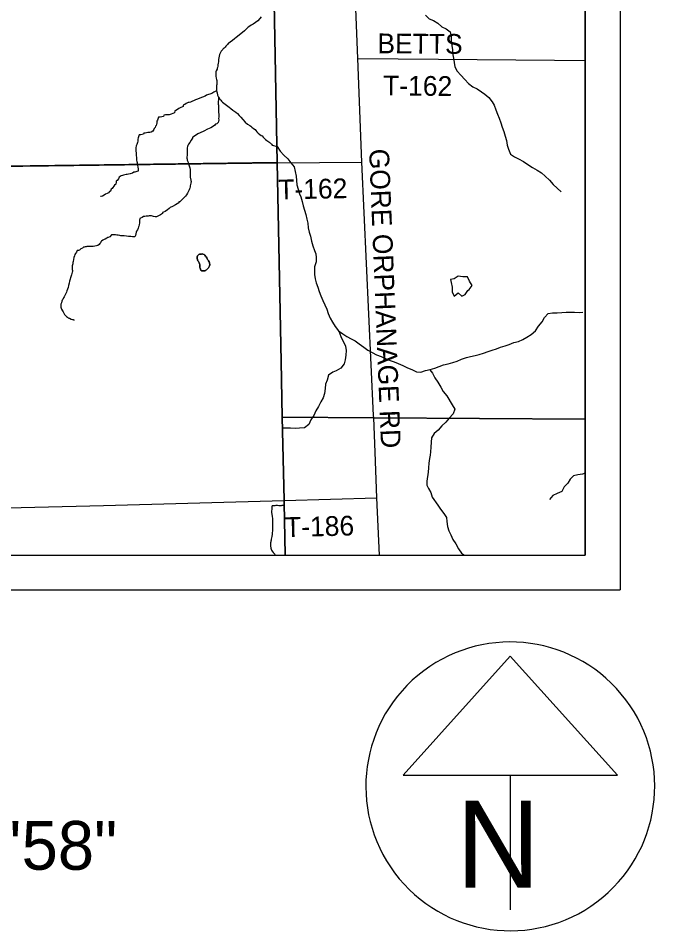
# Model space of a CAD drawing. Extents: x 0 to 34, y 0 to 22.
# Drawn here: x 7.272 to 9.099, y 13.02 to 15.642 of the extents above; entities that cross this region are included whole.
import ezdxf

# ---------------------------------------------------------------- set-up
doc = ezdxf.new("R2010")
doc.units = 0
for name, color, linetype in [('GM_X_Corporation', 7, 'Continuous'), ('GM_X_County_Road', 7, 'Continuous'), ('GM_X_County_Road_Text', 7, 'Continuous'), ('GM_X_Minor_Lake', 7, 'Continuous'), ('GM_X_Minor_River', 7, 'Continuous'), ('GM_X_Township_Road', 7, 'Continuous'), ('GM_X_Township_Road_Text', 7, 'Continuous'), ('SH_Data', 7, 'Continuous'), ('SH_Text', 7, 'Continuous')]:
    doc.layers.add(name, color=color, linetype=linetype)

msp = doc.modelspace()

# ---------------------------------------------------------------- linework, layer by layer
at = {"layer": 'GM_X_Corporation'}
for points in [[(7.992, 16.4534), (8.0153, 15.2273), (8.0262, 14.6555), (8.0297, 14.4963), (8.0349, 14.2572), (8.035, 14.2498), (8.0383, 14.1), (8.9, 14.1), (8.9, 20.9)], [(2.1, 20.2456), (2.1, 14.1), (8.0383, 14.1), (8.035, 14.2498), (8.0349, 14.2572), (8.0297, 14.4963), (8.0262, 14.6555), (8.0153, 15.2273), (7.992, 16.4534)], [(5.9099, 15.7256), (5.9099, 15.2138), (6.1026, 15.2145), (6.7394, 15.212), (6.9496, 15.2134), (8.0153, 15.2273), (7.992, 16.4534)]]:
    msp.add_lwpolyline(points, dxfattribs=at)
for points in [[(7.9196, 19.2769), (7.9387, 18.4008), (7.951, 17.9078), (7.9575, 17.6697), (7.9659, 17.2939), (7.973, 17.0583), (7.9733, 17.0489), (7.9799, 16.8298), (7.992, 16.4534), (8.0153, 15.2273), (8.0262, 14.6555), (8.0297, 14.4963), (8.2922, 14.4944), (8.9, 14.4898), (8.9, 19.6997), (8.7801, 19.7002), (8.7801, 19.2769)], [(3.6901, 15.2048), (3.5209, 15.2041), (2.7366, 15.2014), (2.7422, 14.8151), (2.7753, 14.1537), (2.7761, 14.1), (8.0383, 14.1), (8.035, 14.2498), (8.0349, 14.2572), (8.0297, 14.4963), (8.0262, 14.6555), (8.0153, 15.2273), (6.9496, 15.2134), (6.7394, 15.212), (6.1026, 15.2145), (5.9099, 15.2138), (5.9099, 15.0085), (3.6901, 15.0085)], [(8.0383, 14.1), (8.9, 14.1), (8.9, 14.4898), (8.2922, 14.4944), (8.0297, 14.4963), (8.0349, 14.2572), (8.035, 14.2498)]]:
    msp.add_lwpolyline(points, close=True, dxfattribs=at)
at = {"layer": 'GM_X_County_Road'}
for p, q in [((8.2583, 15.2291), (8.2463, 15.5263)), ((8.2921, 14.5007), (8.2583, 15.2291))]:
    msp.add_line(p, q, dxfattribs=at)
for points in [[(8.2463, 15.5263), (8.2291, 15.9577), (8.215, 16.333), (8.206, 16.5759), (8.1937, 16.9162), (8.1904, 17.0478)], [(8.3094, 14.1), (8.3012, 14.2639), (8.2967, 14.3954), (8.2924, 14.4938), (8.2921, 14.5007)], [(6.9836, 14.2295), (7.1599, 14.2339), (7.5161, 14.2424), (8.0351, 14.2567)]]:
    msp.add_lwpolyline(points, dxfattribs=at)
at = {"layer": 'GM_X_Minor_Lake'}
for points in [[(7.7888, 14.9624), (7.788, 14.9615), (7.7861, 14.9592), (7.7853, 14.9569), (7.7853, 14.9546), (7.7853, 14.9527), (7.7854, 14.952)], [(7.7854, 14.952), (7.7853, 14.9527), (7.7853, 14.9546), (7.7853, 14.9569), (7.7861, 14.9592), (7.788, 14.9615), (7.7888, 14.9624)], [(7.7854, 14.952), (7.7876, 14.9455), (7.7887, 14.9436), (7.7898, 14.9417), (7.791, 14.939), (7.7925, 14.9363), (7.7928, 14.9344), (7.7928, 14.9321), (7.7928, 14.9287), (7.7932, 14.9264), (7.7939, 14.9238), (7.7947, 14.9211), (7.7962, 14.9184), (7.7988, 14.9169), (7.8019, 14.9161), (7.8038, 14.9161), (7.8057, 14.9161), (7.808, 14.9165), (7.8107, 14.918), (7.8126, 14.9191), (7.816, 14.9229), (7.8179, 14.9251), (7.8187, 14.927), (7.8202, 14.9289), (7.8206, 14.9312), (7.8214, 14.9335), (7.8214, 14.9354), (7.821, 14.9373), (7.8207, 14.9392), (7.8196, 14.9422), (7.818, 14.9449), (7.8169, 14.9468), (7.8154, 14.9491), (7.8143, 14.951), (7.8128, 14.9541), (7.8109, 14.9564), (7.8093, 14.9583), (7.8075, 14.961), (7.8052, 14.9629), (7.8018, 14.9644), (7.7995, 14.9648), (7.798, 14.9645)], [(7.798, 14.9645), (7.7995, 14.9648), (7.8018, 14.9644), (7.8052, 14.9629), (7.8075, 14.961), (7.8093, 14.9583), (7.8109, 14.9564), (7.8128, 14.9541), (7.8143, 14.951), (7.8154, 14.9491), (7.8169, 14.9468), (7.818, 14.9449), (7.8196, 14.9422), (7.8207, 14.9392), (7.821, 14.9373), (7.8214, 14.9354), (7.8214, 14.9335), (7.8206, 14.9312), (7.8202, 14.9289), (7.8187, 14.927), (7.8179, 14.9251), (7.816, 14.9229), (7.8126, 14.9191), (7.8107, 14.918), (7.808, 14.9165), (7.8057, 14.9161), (7.8038, 14.9161), (7.8019, 14.9161), (7.7988, 14.9169), (7.7962, 14.9184), (7.7947, 14.9211), (7.7939, 14.9238), (7.7932, 14.9264), (7.7928, 14.9287), (7.7928, 14.9321), (7.7928, 14.9344), (7.7925, 14.9363), (7.791, 14.939), (7.7898, 14.9417), (7.7887, 14.9436), (7.7876, 14.9455), (7.7854, 14.952)], [(7.798, 14.9645), (7.7922, 14.9645), (7.7899, 14.9637), (7.7888, 14.9624)], [(7.7888, 14.9624), (7.7899, 14.9637), (7.7922, 14.9645), (7.798, 14.9645)], [(8.5627, 14.8597), (8.5665, 14.8627), (8.5747, 14.874), (8.5672, 14.887), (8.5617, 14.8993), (8.548, 14.8991), (8.5351, 14.9012), (8.5235, 14.893), (8.5124, 14.892)], [(8.5124, 14.892), (8.515, 14.8832), (8.5175, 14.8695), (8.5177, 14.8558), (8.5232, 14.8432), (8.5348, 14.8529), (8.5453, 14.844), (8.5553, 14.8484), (8.5627, 14.8597)], [(8.5124, 14.892), (8.515, 14.8832), (8.5175, 14.8695), (8.5177, 14.8558), (8.5232, 14.8432), (8.5348, 14.8529), (8.5453, 14.844), (8.5553, 14.8484), (8.5627, 14.8597)], [(8.5627, 14.8597), (8.5665, 14.8627), (8.5747, 14.874), (8.5672, 14.887), (8.5617, 14.8993), (8.548, 14.8991), (8.5351, 14.9012), (8.5235, 14.893), (8.5125, 14.892)]]:
    msp.add_lwpolyline(points, dxfattribs=at)
at = {"layer": 'GM_X_Minor_River'}
for points in [[(7.9695, 15.646), (7.9653, 15.6418), (7.9596, 15.635), (7.9531, 15.6297), (7.9466, 15.6252), (7.9405, 15.6222), (7.9362, 15.6196), (7.932, 15.6162), (7.9267, 15.6113), (7.9209, 15.606), (7.9152, 15.6015), (7.8976, 15.5871), (7.8922, 15.5834), (7.8865, 15.5781), (7.8804, 15.5735), (7.8758, 15.5709), (7.8739, 15.5694), (7.872, 15.5671), (7.8701, 15.5649), (7.8681, 15.5622), (7.8658, 15.5592), (7.8628, 15.5562), (7.8601, 15.5543), (7.8586, 15.5524), (7.857, 15.5505), (7.8543, 15.5475), (7.8532, 15.5456), (7.8513, 15.5422), (7.8509, 15.5403), (7.8497, 15.5376), (7.8489, 15.5334), (7.8478, 15.5285), (7.847, 15.5236), (7.847, 15.519), (7.8462, 15.5171), (7.8454, 15.5129), (7.845, 15.5087), (7.8446, 15.5042), (7.8438, 15.5008), (7.843, 15.4989), (7.8423, 15.4962), (7.84, 15.4913), (7.8392, 15.4886), (7.8388, 15.4852), (7.8388, 15.4803), (7.8391, 15.4753), (7.8398, 15.4696), (7.8413, 15.4658), (7.8417, 15.4631), (7.8421, 15.4601), (7.8421, 15.4555), (7.8417, 15.4517), (7.8413, 15.4487), (7.8412, 15.4453), (7.8408, 15.4422), (7.8408, 15.4361), (7.8412, 15.4331), (7.8423, 15.4281), (7.8438, 15.4213), (7.8468, 15.4152), (7.8498, 15.4106), (7.8513, 15.4087), (7.8532, 15.4064), (7.8555, 15.4037), (7.8585, 15.401), (7.8619, 15.398), (7.8654, 15.3957), (7.8692, 15.3922), (7.8733, 15.3895), (7.8771, 15.3864), (7.8817, 15.383), (7.8874, 15.3776), (7.8961, 15.3726), (7.9014, 15.3684), (7.9059, 15.3631), (7.9109, 15.3577), (7.9166, 15.3512), (7.923, 15.3439), (7.9298, 15.3382), (7.9363, 15.3343), (7.9397, 15.3324), (7.9427, 15.3293), (7.9473, 15.3255), (7.9518, 15.3224), (7.9541, 15.3194), (7.9567, 15.3155), (7.9609, 15.3117), (7.9655, 15.3083), (7.9696, 15.3056), (7.9719, 15.304), (7.9749, 15.3002), (7.9776, 15.2975), (7.9795, 15.296)], [(8.4412, 15.6509), (8.4517, 15.6409), (8.4642, 15.6361), (8.4766, 15.6276), (8.4875, 15.6171), (8.5, 15.6116), (8.5121, 15.6031), (8.5149, 15.5901), (8.5148, 15.5764), (8.5169, 15.5635), (8.519, 15.5513), (8.5192, 15.5372), (8.5213, 15.5277), (8.523, 15.5147), (8.5255, 15.5021), (8.5315, 15.4902), (8.5423, 15.4787), (8.5536, 15.4659), (8.5641, 15.4551), (8.5769, 15.4451), (8.589, 15.4392), (8.6014, 15.431), (8.6113, 15.4244), (8.6233, 15.4147), (8.6326, 15.4024), (8.6378, 15.3928), (8.643, 15.379), (8.6478, 15.3668), (8.6522, 15.3549), (8.6569, 15.3419), (8.6609, 15.3293), (8.6661, 15.3163), (8.6697, 15.303), (8.6734, 15.2907), (8.6758, 15.2778), (8.6791, 15.2656), (8.6854, 15.2518), (8.6963, 15.2444), (8.708, 15.2385), (8.722, 15.2307), (8.7348, 15.2217), (8.748, 15.2132), (8.762, 15.2054), (8.7741, 15.1983), (8.785, 15.1887), (8.7967, 15.1767), (8.8079, 15.1647), (8.8192, 15.1535), (8.8308, 15.1431)], [(7.8412, 15.4331), (7.8366, 15.4316), (7.8332, 15.4293), (7.8278, 15.4263), (7.8118, 15.4211), (7.808, 15.4181), (7.8007, 15.4155), (7.7927, 15.4125), (7.7866, 15.4095), (7.7809, 15.4073), (7.777, 15.4058), (7.7747, 15.405), (7.7717, 15.4035), (7.766, 15.4013), (7.7622, 15.4005), (7.7591, 15.4002), (7.7534, 15.3968), (7.7503, 15.3945), (7.7469, 15.393), (7.745, 15.3927), (7.7449, 15.3881), (7.7362, 15.3851), (7.7323, 15.3832), (7.7289, 15.3798), (7.7243, 15.3772), (7.7213, 15.3761), (7.7205, 15.3708), (7.7109, 15.3666), (7.7048, 15.3648), (7.7014, 15.3648), (7.6945, 15.3645), (7.6896, 15.3637), (7.6888, 15.3603), (7.6793, 15.3581), (7.6747, 15.3578), (7.6716, 15.3494), (7.6697, 15.346), (7.6693, 15.3418), (7.6693, 15.3399), (7.6689, 15.3376), (7.6677, 15.3342), (7.6658, 15.3316), (7.6643, 15.3285), (7.6623, 15.3251), (7.6608, 15.3225), (7.6581, 15.3179), (7.6535, 15.3149), (7.6493, 15.3134), (7.647, 15.3138), (7.6436, 15.3135), (7.6402, 15.3131), (7.6356, 15.3124), (7.6326, 15.3124), (7.6314, 15.309), (7.6238, 15.3071), (7.6188, 15.3068), (7.6157, 15.2981), (7.6153, 15.295), (7.6149, 15.2931), (7.6145, 15.2889), (7.6137, 15.2848), (7.6122, 15.2798), (7.6106, 15.2753), (7.6095, 15.27), (7.6094, 15.2627), (7.6101, 15.2521), (7.6105, 15.2498), (7.6105, 15.2464), (7.6109, 15.2426), (7.6112, 15.2384), (7.6116, 15.2346), (7.6123, 15.2308), (7.6127, 15.2277), (7.613, 15.2228), (7.6142, 15.219), (7.6145, 15.2152), (7.6153, 15.2129), (7.6156, 15.211), (7.6156, 15.2087), (7.6156, 15.2064), (7.6156, 15.203), (7.6125, 15.2019), (7.6095, 15.2011), (7.6064, 15.2), (7.6038, 15.1996), (7.5999, 15.1966), (7.5931, 15.1952), (7.5881, 15.194), (7.5839, 15.1933), (7.5816, 15.1929), (7.5778, 15.1922), (7.574, 15.1911), (7.571, 15.1904), (7.5675, 15.1892), (7.5641, 15.187), (7.561, 15.1859), (7.5599, 15.1809), (7.5553, 15.176), (7.553, 15.1737), (7.5526, 15.1715), (7.5518, 15.1658)], [(7.8468, 15.4152), (7.8459, 15.3954), (7.8463, 15.3924), (7.8463, 15.3897), (7.8463, 15.3851), (7.8462, 15.3802), (7.8462, 15.3771), (7.8466, 15.3733), (7.8469, 15.3703), (7.8473, 15.368), (7.8473, 15.3661), (7.8477, 15.3634), (7.8473, 15.3608), (7.8473, 15.3577), (7.8469, 15.3539), (7.8472, 15.3501), (7.8472, 15.3482), (7.8468, 15.346), (7.8453, 15.3422), (7.8414, 15.3388), (7.8384, 15.338), (7.8361, 15.3354), (7.8319, 15.3316), (7.825, 15.3275), (7.8151, 15.323), (7.8048, 15.3173), (7.7941, 15.3128), (7.7872, 15.3098), (7.7746, 15.3016), (7.7723, 15.3008), (7.7723, 15.2978), (7.7681, 15.2921), (7.7642, 15.2853), (7.7604, 15.28), (7.7585, 15.2766), (7.7573, 15.2732), (7.7565, 15.2697), (7.7565, 15.2644), (7.7568, 15.2606), (7.7568, 15.2572), (7.7568, 15.2526), (7.7564, 15.2477), (7.7556, 15.2439), (7.756, 15.2401), (7.7567, 15.2374), (7.7571, 15.2344), (7.7582, 15.2306), (7.7597, 15.2264), (7.7612, 15.221), (7.7642, 15.2123), (7.7649, 15.2073), (7.7653, 15.2027), (7.7653, 15.1986), (7.7652, 15.1925), (7.7652, 15.186), (7.7663, 15.1811), (7.7671, 15.1788), (7.7674, 15.1757), (7.7678, 15.1731), (7.7674, 15.1685), (7.7662, 15.1643), (7.7655, 15.1609), (7.7651, 15.1582), (7.7643, 15.1544), (7.7631, 15.1522), (7.7624, 15.1495), (7.7604, 15.145), (7.7577, 15.1397), (7.7547, 15.1344), (7.752, 15.1309), (7.7351, 15.1147), (7.7325, 15.1143), (7.7324, 15.1121), (7.7229, 15.106), (7.7145, 15.1012), (7.708, 15.0982), (7.7049, 15.0955), (7.7, 15.0914), (7.6938, 15.0865), (7.6885, 15.0846), (7.6862, 15.0842), (7.6858, 15.0812), (7.6801, 15.0774), (7.6763, 15.0755), (7.6743, 15.0744), (7.6709, 15.0725), (7.6682, 15.0714), (7.6644, 15.0714), (7.6595, 15.0726), (7.6542, 15.0742), (7.65, 15.0746), (7.6477, 15.0746), (7.6442, 15.0739), (7.6393, 15.0731), (7.6347, 15.0724), (7.6309, 15.0721), (7.6275, 15.0698), (7.6225, 15.0679)], [(7.9795, 15.296), (7.9814, 15.2933), (7.9852, 15.2906), (7.9886, 15.2887), (7.9909, 15.2872), (7.9932, 15.2853), (7.9954, 15.2841), (7.9988, 15.2803), (8.0011, 15.2776), (8.0154, 15.2738)], [(8.0154, 15.2738), (8.0238, 15.2599), (8.0343, 15.2487), (8.0456, 15.2383), (8.0546, 15.2264), (8.0635, 15.2148), (8.0672, 15.2014), (8.0696, 15.1885), (8.071, 15.1759), (8.072, 15.1633), (8.0756, 15.1507), (8.0796, 15.1381), (8.0829, 15.1286), (8.0865, 15.116), (8.0894, 15.103), (8.0934, 15.0904), (8.0974, 15.0782), (8.1007, 15.0652), (8.1028, 15.053), (8.1045, 15.0397), (8.1074, 15.0274), (8.111, 15.0156), (8.1139, 15.0019), (8.1179, 14.9881), (8.1226, 14.9751), (8.1259, 14.9652), (8.1273, 14.9549), (8.1271, 14.942), (8.1227, 14.928), (8.1219, 14.9185), (8.1224, 14.9055), (8.1242, 14.8937), (8.1271, 14.8823), (8.1315, 14.8697), (8.1358, 14.8567), (8.1406, 14.8444), (8.1458, 14.8314), (8.1517, 14.8188), (8.1576, 14.8065), (8.1612, 14.7939), (8.1671, 14.7802), (8.1735, 14.7686), (8.182, 14.7564), (8.191, 14.7437), (8.2034, 14.7351), (8.2148, 14.7281), (8.2276, 14.7211), (8.2393, 14.7152), (8.251, 14.7063), (8.2642, 14.6973), (8.2759, 14.6884), (8.3008, 14.6755), (8.3137, 14.6707), (8.3266, 14.6644), (8.3398, 14.6589), (8.3512, 14.6549), (8.3629, 14.6502), (8.3762, 14.6443), (8.389, 14.6376), (8.4019, 14.6329), (8.4148, 14.6266), (8.4281, 14.6253), (8.4411, 14.6296), (8.4544, 14.6328), (8.4674, 14.6364), (8.4801, 14.642), (8.4931, 14.6459), (8.5057, 14.6496), (8.5195, 14.6535), (8.5324, 14.6571), (8.5447, 14.663), (8.5585, 14.667), (8.5699, 14.6703), (8.5833, 14.6735), (8.5948, 14.676), (8.6074, 14.6796), (8.6208, 14.6851), (8.6323, 14.6883), (8.6445, 14.6927), (8.656, 14.6971), (8.6694, 14.7007), (8.6816, 14.7047), (8.6946, 14.7106), (8.708, 14.7138), (8.7202, 14.7189), (8.7325, 14.726), (8.7448, 14.7334), (8.7568, 14.7438), (8.7657, 14.757), (8.7758, 14.7702), (8.7832, 14.7822), (8.7936, 14.7935), (8.8058, 14.796), (8.8188, 14.7958), (8.8321, 14.7963), (8.8447, 14.7976), (8.8569, 14.7978), (8.8691, 14.7977), (8.8828, 14.7971), (8.8927, 14.7973)], [(7.5518, 15.1658), (7.548, 15.1624), (7.5411, 15.1533), (7.5384, 15.1506), (7.5364, 15.1457), (7.5334, 15.1442), (7.5307, 15.1408), (7.5269, 15.1385), (7.5223, 15.1363), (7.5185, 15.134), (7.5139, 15.1314), (7.5093, 15.1299), (7.5082, 15.1299)], [(7.6225, 15.0679), (7.6206, 15.0672), (7.6198, 15.0622), (7.6198, 15.0573), (7.6198, 15.0542), (7.619, 15.0489), (7.6178, 15.0451), (7.617, 15.0425), (7.6155, 15.0387), (7.6136, 15.0345), (7.6116, 15.0307), (7.6105, 15.0273), (7.6081, 15.0182), (7.6066, 15.014), (7.5997, 15.0145), (7.5944, 15.0149), (7.5879, 15.0149), (7.5826, 15.0157), (7.5758, 15.0165), (7.5697, 15.0166), (7.5666, 15.017), (7.5628, 15.0181), (7.5586, 15.0185), (7.5567, 15.0185), (7.5544, 15.0189), (7.5506, 15.0201), (7.5468, 15.0201), (7.5434, 15.0202), (7.5396, 15.0194), (7.5342, 15.0137), (7.5296, 15.0126), (7.5277, 15.0123), (7.5258, 15.01), (7.5209, 15.0074), (7.5178, 15.0063), (7.5144, 15.0044), (7.5109, 15.0017), (7.5086, 14.9999), (7.5075, 14.9972), (7.5059, 14.9949), (7.504, 14.9919), (7.4998, 14.9889), (7.4964, 14.9881), (7.4914, 14.987), (7.4865, 14.9867), (7.4743, 14.986), (7.472, 14.9864), (7.4689, 14.9864), (7.4663, 14.9857), (7.4636, 14.9849), (7.4605, 14.9842), (7.4586, 14.9842), (7.4563, 14.9812), (7.451, 14.9801), (7.4476, 14.9759), (7.4441, 14.9752), (7.4411, 14.9744), (7.4384, 14.9699), (7.4361, 14.9661), (7.4345, 14.9635), (7.433, 14.9593), (7.4311, 14.9547), (7.4299, 14.9494), (7.4295, 14.9437), (7.4287, 14.9399), (7.4279, 14.9365), (7.4267, 14.9308), (7.426, 14.9251), (7.4263, 14.9217), (7.4267, 14.9198), (7.4271, 14.9175), (7.427, 14.9144), (7.4263, 14.9122), (7.4259, 14.9088), (7.4247, 14.9046), (7.4239, 14.9019), (7.4189, 14.8867), (7.4173, 14.8814), (7.4158, 14.8746), (7.4146, 14.8689), (7.4131, 14.8636), (7.4115, 14.8586), (7.4103, 14.8556), (7.4092, 14.853), (7.4076, 14.8492), (7.4057, 14.8458), (7.4038, 14.8416), (7.4019, 14.8386), (7.3996, 14.8344), (7.398, 14.8321), (7.3969, 14.8295), (7.3953, 14.8245), (7.3938, 14.8211), (7.3934, 14.8181), (7.3934, 14.8143), (7.3941, 14.8116), (7.3945, 14.8093), (7.396, 14.8059), (7.3983, 14.8013), (7.4005, 14.7983), (7.4024, 14.7948)], [(7.4024, 14.7948), (7.4047, 14.7914), (7.4073, 14.7879), (7.41, 14.7853), (7.4126, 14.783), (7.4149, 14.7818), (7.4172, 14.7806), (7.4191, 14.7803), (7.4233, 14.7776), (7.4271, 14.7768), (7.4297, 14.7764), (7.4313, 14.776), (7.4316, 14.7741)], [(8.191, 14.7436), (8.1936, 14.7387), (8.1984, 14.7249), (8.2054, 14.7123), (8.2117, 14.7), (8.2134, 14.6874), (8.2125, 14.6738), (8.2108, 14.6609), (8.2072, 14.6488), (8.1979, 14.6371), (8.1848, 14.6289), (8.1753, 14.6253), (8.1626, 14.6167), (8.1582, 14.6027), (8.1539, 14.591), (8.1529, 14.5781), (8.1508, 14.5644), (8.1468, 14.5512), (8.1406, 14.5399), (8.1336, 14.5267), (8.1261, 14.5139), (8.1199, 14.501), (8.1117, 14.4886), (8.1062, 14.475), (8.0931, 14.4657), (8.0794, 14.4644), (8.0672, 14.4638), (8.0535, 14.4644), (8.0313, 14.4641)], [(8.4535, 14.6326), (8.4536, 14.6323), (8.4608, 14.6225), (8.4678, 14.6094), (8.4768, 14.5964), (8.485, 14.5826), (8.492, 14.5695), (8.5025, 14.5572), (8.5174, 14.5311), (8.5252, 14.5192), (8.5208, 14.5056), (8.5092, 14.4932), (8.4996, 14.4816), (8.488, 14.4707), (8.4775, 14.4591), (8.4656, 14.4487), (8.4586, 14.4362), (8.4573, 14.4237), (8.4559, 14.41), (8.4557, 14.3963), (8.4545, 14.3869), (8.4524, 14.3774), (8.4507, 14.3641), (8.4494, 14.3508), (8.4484, 14.3383), (8.445, 14.3125), (8.4449, 14.3003), (8.4497, 14.2907), (8.456, 14.2792), (8.4604, 14.2666), (8.4761, 14.2436), (8.4843, 14.2313), (8.4933, 14.2197), (8.5011, 14.2082), (8.5024, 14.196), (8.5042, 14.1823), (8.5078, 14.1693), (8.5137, 14.1578), (8.5192, 14.1448), (8.5278, 14.1318), (8.5356, 14.118), (8.5446, 14.1057), (8.5532, 14.1)], [(8.9, 14.3347), (8.8919, 14.3323), (8.8786, 14.3306), (8.8663, 14.3278), (8.8567, 14.318), (8.8493, 14.306), (8.8392, 14.2955), (8.8322, 14.2823), (8.8192, 14.2768), (8.8065, 14.2709), (8.7972, 14.2592)], [(8.0362, 14.2423), (8.0307, 14.2422), (8.0288, 14.2419), (8.0261, 14.2415), (8.0227, 14.2415), (8.0197, 14.2415), (8.0159, 14.2419), (8.0132, 14.242), (8.0113, 14.242), (8.0079, 14.2416), (8.0037, 14.2416), (8.001, 14.2417), (7.9998, 14.2398), (7.9994, 14.2345), (7.999, 14.223), (8.0001, 14.2166), (8.0005, 14.212), (8.0008, 14.2101), (8.0012, 14.2063), (8.0016, 14.2029), (8.0019, 14.1995), (8.0019, 14.1968), (8.0015, 14.1873), (8.0014, 14.1808), (8.0018, 14.1778), (8.0014, 14.1683), (8.001, 14.1645), (8.0009, 14.1603), (7.9998, 14.1535), (7.9982, 14.1455), (7.9978, 14.1428), (7.997, 14.1394), (7.9966, 14.1375), (7.9962, 14.1348), (7.9962, 14.1329), (7.9958, 14.1307), (7.9958, 14.1284), (7.9958, 14.1261), (7.9969, 14.1196), (7.9988, 14.1143), (8.0011, 14.1109), (8.0037, 14.107), (8.006, 14.104), (8.0083, 14.1021), (8.0098, 14.1002), (8.0099, 14.1)]]:
    msp.add_lwpolyline(points, dxfattribs=at)
at = {"layer": 'GM_X_Township_Road'}
for p, q in [((8.2583, 15.2291), (8.2463, 15.5263)), ((6.9498, 15.2128), (8.0155, 15.2267)), ((8.0155, 15.2267), (8.2583, 15.2291)), ((8.0351, 14.2567), (8.3012, 14.2639))]:
    msp.add_line(p, q, dxfattribs=at)
msp.add_lwpolyline([(8.2463, 15.5263), (8.4783, 15.5241), (8.8115, 15.5217), (8.9, 15.5209)], dxfattribs=at)
at = {"layer": 'SH_Data'}
for p, q in [((9, 21), (9, 14)), ((8.9, 20.9), (8.9, 14.1)), ((2.1, 14.1), (8.9, 14.1)), ((2, 14), (9, 14)), ((8.6845, 13.809), (8.3769, 13.4678)), ((8.9921, 13.4678), (8.6845, 13.809)), ((8.3769, 13.4678), (8.9921, 13.4678)), ((8.6845, 13.4678), (8.6845, 13.081)), ((8.6845, 13.4353), (8.6845, 13.4353)), ((8.6845, 13.4353), (8.6845, 13.4353))]:
    msp.add_line(p, q, dxfattribs=at)
msp.add_arc((8.6845, 13.4353), 0.4148, 129.7798, 129.7633, dxfattribs=at)

# ---------------------------------------------------------------- texts
at = {"layer": 'GM_X_County_Road_Text'}
msp.add_text('GORE ORPHANAGE RD', height=0.056818, rotation=272.2962, dxfattribs=at).set_placement((8.2791, 15.2661))
at = {"layer": 'GM_X_Township_Road_Text'}
for s, rotation, p in [('BETTS', 359.5509, (8.3027, 15.5416)), ('T-162', 359.4386, (8.3191, 15.4206)), ('T-162', 1.1238, (8.0187, 15.1215)), ('T-186', 1.4033, (8.0383, 14.1515))]:
    msp.add_text(s, height=0.05682, rotation=rotation, dxfattribs=at).set_placement(p)
at = {"layer": 'SH_Data'}
msp.add_text('N', height=0.25, dxfattribs=at).set_placement((8.5292, 13.1439))
at = {"layer": 'SH_Text'}
msp.add_text('LATITUDE:  N41°14\'17"     LONGITUDE:  W82°21\'58"', height=0.14, dxfattribs=at).set_placement((3.071, 13.1958))

doc.saveas('drawing.dxf')
